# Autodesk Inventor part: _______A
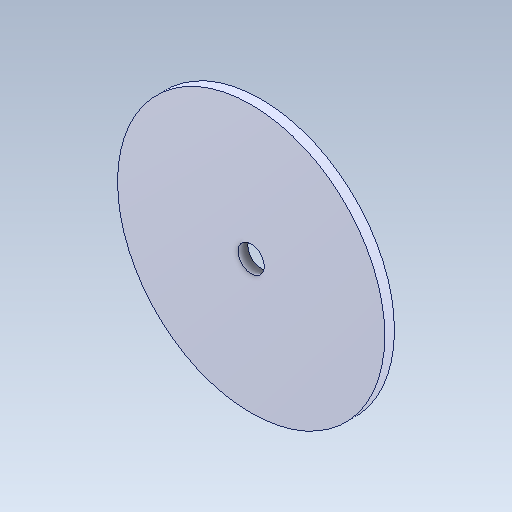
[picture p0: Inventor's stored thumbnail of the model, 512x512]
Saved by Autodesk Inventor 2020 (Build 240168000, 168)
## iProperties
Created: 2017-09
Part Number: _______A
Material: Générique
Document SubType Name: Modeling
Designer: bruno
Density: 1 g/cm^3
Appearance: Par défaut
Author: bruno
Sending System: SolidWorks 2016
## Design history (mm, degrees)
feature "Importée1"
node "Solide1"
